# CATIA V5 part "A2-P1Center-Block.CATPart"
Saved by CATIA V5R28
Part number: Center-Block
Revision: ANY
Definition: UNKNOWN
Nomenclature: Center-Block
Source: Unknown
Bounding box of the stored display mesh (mm): x -31 to 31, y -24 to 24, z -24 to 24
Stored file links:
  E:\TP Catia - Documents\Additional Exercise\Contrôle\Problem-3-Section-J\A2-P1Center-Block.CATPart
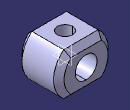
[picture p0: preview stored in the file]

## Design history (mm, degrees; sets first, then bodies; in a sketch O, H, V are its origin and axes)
Body1 "Imported1" (main body)
  Solid1: solid without history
